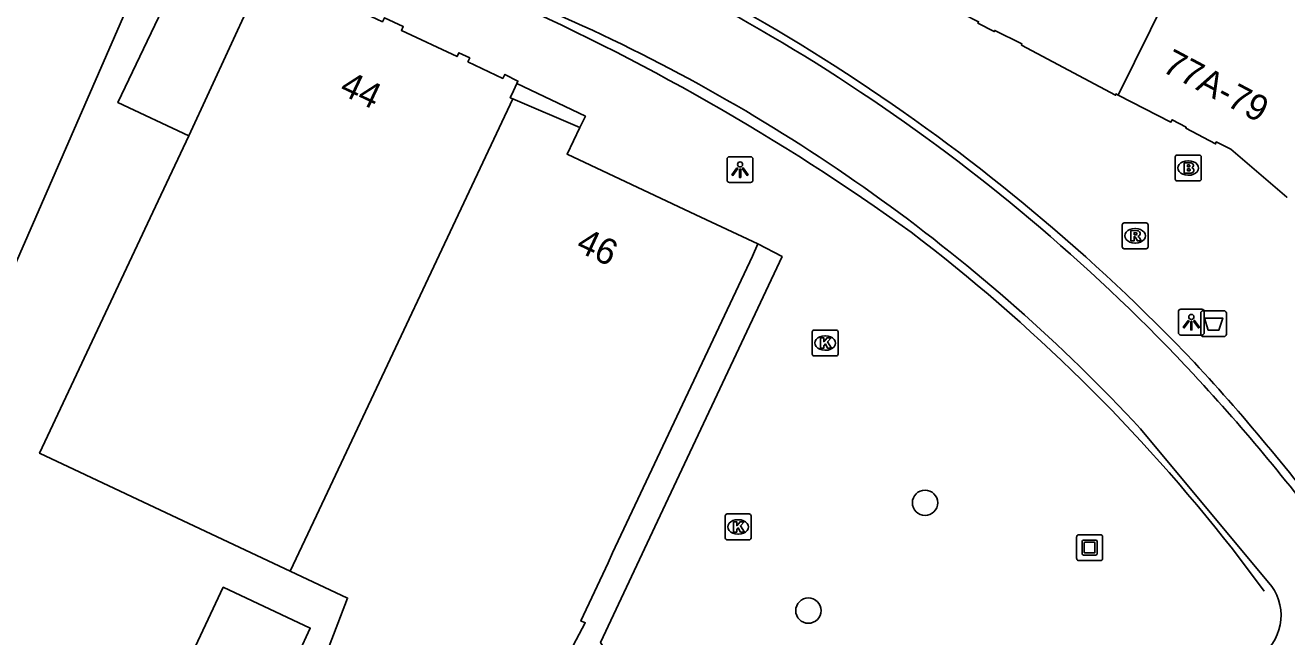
# Model space of a CAD drawing. Extents: x 161087 to 161922, y 382574 to 383873.
# Drawn here: x 161588.59 to 161637.33, y 382995.31 to 383018.93 of the extents above; entities that cross this region are included whole.
import ezdxf

# ---------------------------------------------------------------- set-up
doc = ezdxf.new("R2010")
doc.units = 0
for name, color, linetype in [('IMGEO_Afvalbak', 7, 'Continuous'), ('IMGEO_Boom', 7, 'Continuous'), ('IMGEO_Brandkraan', 7, 'Continuous'), ('IMGEO_Kolk', 7, 'Continuous'), ('IMGEO_Kunstobject', 7, 'Continuous'), ('IMGEO_Lichtpunt', 7, 'Continuous'), ('IMGEO_Lijnafwatering', 7, 'Continuous'), ('IMGEO_Pand', 7, 'Continuous'), ('IMGEO_Pand_nummerreeks', 7, 'Continuous'), ('IMGEO_Pand_overbouw', 7, 'Continuous'), ('IMGEO_Rioolput', 7, 'Continuous'), ('IMGEO_Voetgangersgebied_gesloten', 7, 'Continuous'), ('IMGEO_Voetgangersgebied_open', 7, 'Continuous')]:
    doc.layers.add(name, color=color, linetype=linetype)

msp = doc.modelspace()

# ---------------------------------------------------------------- linework, layer by layer
at = {"layer": 'IMGEO_Afvalbak'}
for p, q in [((161634.008, 383007.005), (161634.008, 383007.805)), ((161634.008, 383007.805), (161634.008, 383007.005)), ((161634.108, 383007.905), (161634.898, 383007.905)), ((161634.898, 383007.905), (161634.108, 383007.905)), ((161634.998, 383007.805), (161634.998, 383007.005)), ((161634.998, 383007.005), (161634.998, 383007.805)), ((161634.898, 383006.905), (161634.108, 383006.905)), ((161634.108, 383006.905), (161634.898, 383006.905))]:
    msp.add_line(p, q, dxfattribs=at)
msp.add_lwpolyline([(161634.151, 383007.619), (161634.855, 383007.619), (161634.706, 383007.149), (161634.3, 383007.149), (161634.151, 383007.619)], dxfattribs=at)
for centre, start, end in [((161634.108, 383007.805), 90, 180), ((161634.108, 383007.805), 90, 180), ((161634.898, 383007.805), 0, 90), ((161634.898, 383007.805), 360, 90), ((161634.108, 383007.005), 180, 270), ((161634.108, 383007.005), 180, 270), ((161634.898, 383007.005), 270, 0), ((161634.898, 383007.005), 270, 0)]:
    msp.add_arc(centre, 0.1, start, end, dxfattribs=at)
at = {"layer": 'IMGEO_Boom'}
for centre in [(161623.355, 383000.49), (161618.849, 382996.324)]:
    msp.add_circle(centre, 0.489, dxfattribs=at)
at = {"layer": 'IMGEO_Brandkraan'}
for p, q in [((161633.025, 383012.991), (161633.025, 383013.843)), ((161633.1, 383013.917), (161633.952, 383013.917)), ((161633.513, 383013.697), (161633.538, 383013.697)), ((161634.026, 383013.843), (161634.026, 383012.991)), ((161633.952, 383012.917), (161633.1, 383012.917)), ((161633.536, 383013.137), (161633.511, 383013.137))]:
    msp.add_line(p, q, dxfattribs=at)
for points in [[(161633.025, 383012.991), (161633.025, 383013.843)], [(161633.1, 383013.917), (161633.952, 383013.917)], [(161634.026, 383013.843), (161634.026, 383012.991)], [(161633.373, 383013.617), (161633.373, 383013.217), (161633.586, 383013.217)], [(161633.604, 383013.617), (161633.373, 383013.617)], [(161633.552, 383013.536), (161633.498, 383013.536), (161633.498, 383013.46)], [(161633.498, 383013.46), (161633.551, 383013.46)], [(161633.56, 383013.384), (161633.498, 383013.384), (161633.498, 383013.303)], [(161633.498, 383013.303), (161633.56, 383013.303)], [(161633.952, 383012.917), (161633.1, 383012.917)]]:
    msp.add_lwpolyline(points, dxfattribs=at)
for centre, radius, start, end in [((161633.102, 383013.841), 0.0765, 91.552, 178.448), ((161633.102, 383013.841), 0.0765, 91.552, 178.448), ((161633.95, 383013.841), 0.0765, 1.552, 88.448), ((161633.95, 383013.841), 0.0765, 1.552, 88.448), ((161633.553, 383013.498), 0.0379, 267.8285, 90.9355), ((161633.561, 383013.343), 0.0404, 269.8759, 90.5077), ((161633.592, 383013.468), 0.251, 268.6676, 293.5347), ((161633.608, 383013.472), 0.145, 59.4692, 91.5367), ((161633.633, 383013.519), 0.0922, 285.5137, 58.1501), ((161633.638, 383013.327), 0.105, 301.3115, 78.989), ((161633.102, 383012.993), 0.0765, 181.552, 268.448), ((161633.102, 383012.993), 0.0765, 181.552, 268.448), ((161633.95, 383012.993), 0.0765, 271.552, 358.448), ((161633.95, 383012.993), 0.0765, 271.552, 358.448)]:
    msp.add_arc(centre, radius, start, end, dxfattribs=at)
for centre, major_axis, ratio, start_param, end_param in [((161633.512, 383013.417), (-0.387, 0.002), 0.722429, 4.712389, 7.853982), ((161633.537, 383013.417), (-0.39, 0.002), 0.717154, 1.570796, 4.712389)]:
    msp.add_ellipse(centre, major_axis=major_axis, ratio=ratio, start_param=start_param, end_param=end_param, dxfattribs=at)
at = {"layer": 'IMGEO_Kolk'}
for p, q in [((161618.997, 383006.233), (161618.997, 383007.085)), ((161619.072, 383007.159), (161619.924, 383007.159)), ((161619.485, 383006.939), (161619.51, 383006.939)), ((161619.998, 383007.085), (161619.998, 383006.233)), ((161619.508, 383006.379), (161619.483, 383006.379)), ((161619.924, 383006.159), (161619.072, 383006.159)), ((161615.709, 383000.056), (161616.561, 383000.056)), ((161615.634, 382999.13), (161615.634, 382999.982)), ((161616.122, 382999.836), (161616.147, 382999.836)), ((161616.635, 382999.982), (161616.635, 382999.13)), ((161616.561, 382999.056), (161615.709, 382999.056)), ((161616.145, 382999.276), (161616.12, 382999.276))]:
    msp.add_line(p, q, dxfattribs=at)
for points in [[(161618.997, 383006.233), (161618.997, 383007.085)], [(161619.072, 383007.159), (161619.924, 383007.159)], [(161619.318, 383006.859), (161619.441, 383006.859), (161619.441, 383006.708), (161619.571, 383006.859), (161619.735, 383006.859), (161619.589, 383006.708), (161619.742, 383006.459), (161619.59, 383006.459), (161619.505, 383006.623), (161619.441, 383006.556), (161619.441, 383006.459), (161619.318, 383006.459), (161619.318, 383006.859)], [(161619.998, 383007.085), (161619.998, 383006.233)], [(161619.924, 383006.159), (161619.072, 383006.159)], [(161615.709, 383000.056), (161616.561, 383000.056)], [(161615.634, 382999.13), (161615.634, 382999.982)], [(161615.955, 382999.756), (161616.078, 382999.756), (161616.078, 382999.605), (161616.208, 382999.756), (161616.372, 382999.756), (161616.226, 382999.605), (161616.379, 382999.356), (161616.227, 382999.356), (161616.142, 382999.52), (161616.078, 382999.453), (161616.078, 382999.356), (161615.955, 382999.356), (161615.955, 382999.756)], [(161616.635, 382999.982), (161616.635, 382999.13)], [(161616.561, 382999.056), (161615.709, 382999.056)]]:
    msp.add_lwpolyline(points, dxfattribs=at)
for centre, start, end in [((161619.074, 383007.083), 91.552, 178.448), ((161619.074, 383007.083), 91.552, 178.448), ((161619.922, 383007.083), 1.552, 88.448), ((161619.922, 383007.083), 1.552, 88.448), ((161619.074, 383006.235), 181.552, 268.448), ((161619.074, 383006.235), 181.552, 268.448), ((161619.922, 383006.235), 271.552, 358.448), ((161619.922, 383006.235), 271.552, 358.448), ((161615.711, 382999.98), 91.552, 178.448), ((161615.711, 382999.98), 91.552, 178.448), ((161616.559, 382999.98), 1.552, 88.448), ((161616.559, 382999.98), 1.552, 88.448), ((161615.711, 382999.132), 181.552, 268.448), ((161615.711, 382999.132), 181.552, 268.448), ((161616.559, 382999.132), 271.552, 358.448), ((161616.559, 382999.132), 271.552, 358.448)]:
    msp.add_arc(centre, 0.0765, start, end, dxfattribs=at)
for centre, major_axis, ratio, start_param, end_param in [((161619.484, 383006.659), (-0.387, 0.002), 0.722429, 4.712389, 7.853982), ((161619.509, 383006.659), (-0.39, 0.002), 0.717154, 1.570796, 4.712389), ((161616.121, 382999.556), (-0.387, 0.002), 0.722429, 4.712389, 7.853982), ((161616.146, 382999.556), (-0.39, 0.002), 0.717154, 1.570796, 4.712389)]:
    msp.add_ellipse(centre, major_axis=major_axis, ratio=ratio, start_param=start_param, end_param=end_param, dxfattribs=at)
at = {"layer": 'IMGEO_Kunstobject'}
for p, q in [((161629.214, 382999.173), (161629.214, 382998.332)), ((161629.214, 382999.173), (161629.214, 382998.332)), ((161630.13, 382999.257), (161629.289, 382999.257)), ((161630.13, 382999.257), (161629.289, 382999.257)), ((161629.478, 382999.045), (161629.952, 382999.045)), ((161630.214, 382998.341), (161630.214, 382999.182)), ((161630.214, 382998.341), (161630.214, 382999.182)), ((161629.428, 382998.521), (161629.428, 382998.995)), ((161629.508, 382998.945), (161629.508, 382998.571)), ((161629.902, 382998.965), (161629.528, 382998.965)), ((161629.528, 382998.551), (161629.902, 382998.551)), ((161629.922, 382998.571), (161629.922, 382998.945)), ((161630.002, 382998.995), (161630.002, 382998.521)), ((161629.298, 382998.257), (161630.139, 382998.257)), ((161629.298, 382998.257), (161630.139, 382998.257)), ((161629.952, 382998.471), (161629.478, 382998.471))]:
    msp.add_line(p, q, dxfattribs=at)
for centre, radius, start, end in [((161629.292, 382999.179), 0.0779, 92.4484, 184.2845), ((161629.292, 382999.179), 0.0779, 92.4484, 184.2845), ((161629.478, 382998.995), 0.05, 90, 180), ((161629.952, 382998.995), 0.05, 360, 90), ((161630.136, 382999.179), 0.0779, 2.4484, 94.2845), ((161630.136, 382999.179), 0.0779, 2.4484, 94.2845), ((161629.528, 382998.945), 0.02, 90, 180), ((161629.528, 382998.571), 0.02, 180, 270), ((161629.902, 382998.945), 0.02, 360, 90), ((161629.902, 382998.571), 0.02, 270, 0), ((161629.292, 382998.335), 0.0779, 182.4484, 274.2845), ((161629.292, 382998.335), 0.0779, 182.4484, 274.2845), ((161629.478, 382998.521), 0.05, 180, 270), ((161629.952, 382998.521), 0.05, 270, 0), ((161630.136, 382998.335), 0.0779, 272.4484, 4.2845), ((161630.136, 382998.335), 0.0779, 272.4484, 4.2845)]:
    msp.add_arc(centre, radius, start, end, dxfattribs=at)
at = {"layer": 'IMGEO_Lichtpunt'}
for p, q in [((161615.71, 383013.759), (161615.71, 383012.952)), ((161615.71, 383013.759), (161615.71, 383012.952)), ((161616.612, 383013.854), (161615.804, 383013.854)), ((161616.612, 383013.854), (161615.804, 383013.854)), ((161616.706, 383012.952), (161616.706, 383013.759)), ((161616.706, 383012.952), (161616.706, 383013.759)), ((161615.804, 383012.858), (161616.612, 383012.858)), ((161615.804, 383012.858), (161616.612, 383012.858)), ((161633.146, 383007.868), (161633.146, 383007.061)), ((161633.146, 383007.868), (161633.146, 383007.061)), ((161634.048, 383007.963), (161633.24, 383007.963)), ((161634.048, 383007.963), (161633.24, 383007.963)), ((161634.142, 383007.061), (161634.142, 383007.868)), ((161634.142, 383007.061), (161634.142, 383007.868)), ((161633.24, 383006.967), (161634.048, 383006.967)), ((161633.24, 383006.967), (161634.048, 383006.967))]:
    msp.add_line(p, q, dxfattribs=at)
for points in [[(161616.084, 383013.423), (161616.123, 383013.395), (161615.935, 383013.133), (161615.897, 383013.16), (161616.084, 383013.423)], [(161616.186, 383013.375), (161616.233, 383013.375), (161616.233, 383013.053), (161616.186, 383013.053), (161616.186, 383013.375)], [(161616.296, 383013.395), (161616.334, 383013.422), (161616.521, 383013.16), (161616.482, 383013.132), (161616.296, 383013.395)], [(161633.52, 383007.532), (161633.559, 383007.504), (161633.371, 383007.242), (161633.333, 383007.269), (161633.52, 383007.532)], [(161633.622, 383007.484), (161633.669, 383007.484), (161633.669, 383007.162), (161633.622, 383007.162), (161633.622, 383007.484)], [(161633.732, 383007.504), (161633.77, 383007.531), (161633.957, 383007.269), (161633.918, 383007.241), (161633.732, 383007.504)]]:
    msp.add_lwpolyline(points, dxfattribs=at)
for centre in [(161616.209, 383013.557), (161633.645, 383007.666)]:
    msp.add_circle(centre, 0.0994, dxfattribs=at)
for centre, start, end in [((161615.804, 383013.759), 90, 180), ((161615.804, 383013.759), 90, 180), ((161616.612, 383013.759), 0, 90), ((161616.612, 383013.759), 0, 90), ((161615.804, 383012.952), 180, 270), ((161615.804, 383012.952), 180, 270), ((161616.612, 383012.952), 270, 0), ((161616.612, 383012.952), 270, 360), ((161633.24, 383007.868), 90, 180), ((161633.24, 383007.868), 90, 180), ((161634.048, 383007.868), 0, 90), ((161634.048, 383007.868), 0, 90), ((161633.24, 383007.061), 180, 270), ((161633.24, 383007.061), 180, 270), ((161634.048, 383007.061), 270, 0), ((161634.048, 383007.061), 270, 360)]:
    msp.add_arc(centre, 0.0946, start, end, dxfattribs=at)
at = {"layer": 'IMGEO_Lijnafwatering'}
msp.add_lwpolyline([(161636.459, 382997.073), (161635.231, 382998.711)], dxfattribs=at)
for centre, radius, start, end in [((161579.171, 382953.81), 75.463, 43.66446, 69.43511), ((161571.511, 382939.689), 87.797, 54.24429, 66.39142), ((161581.513, 382956.576), 68.271, 38.10929, 52.77417), ((161571.231, 382948.219), 85.079, 36.64081, 42.69607)]:
    msp.add_arc(centre, radius, start, end, dxfattribs=at)
at = {"layer": 'IMGEO_Pand'}
for points in [[(161640.737, 383034.802), (161638.738, 383032.194), (161635.573, 383026.502), (161635.821, 383026.367), (161630.82, 383016.229)], [(161593.938, 383022.832), (161587.851, 383008.898), (161582.318, 383000.765), (161580.327, 383001.446)], [(161597.828, 383020.995), (161597.271, 383019.756), (161594.908, 383014.656), (161593.731, 383012.151), (161589.147, 383002.399), (161594.251, 383000), (161598.828, 382997.849)], [(161597.828, 383020.995), (161597.945, 383021.255), (161597.998, 383021.332), (161598.514, 383021.101), (161598.437, 383020.938), (161599.775, 383020.306), (161599.845, 383020.467), (161600.281, 383020.265), (161600.207, 383020.111), (161602.39, 383019.064), (161602.469, 383019.223), (161603.195, 383018.878), (161603.127, 383018.732), (161605.275, 383017.721), (161605.346, 383017.87), (161605.765, 383017.67), (161605.696, 383017.518), (161607.043, 383016.877), (161607.126, 383017.031), (161607.624, 383016.773), (161607.579, 383016.676)], [(161630.82, 383016.229), (161630.721, 383016.28), (161630.716, 383016.23), (161627.079, 383018.166), (161627.1, 383018.21), (161626.051, 383018.728), (161626.028, 383018.684), (161625.395, 383019.012), (161625.424, 383019.068), (161622.995, 383020.312)], [(161607.426, 383016.088), (161607.328, 383016.13), (161607.453, 383016.403), (161607.579, 383016.676)], [(161607.426, 383016.088), (161599.842, 383000), (161598.828, 382997.849)], [(161610.019, 383014.978), (161607.426, 383016.088)], [(161637.344, 383012.284), (161637.333, 383012.295), (161635.168, 383014.151), (161634.604, 383014.423), (161634.582, 383014.346), (161633.431, 383014.957), (161633.451, 383014.988), (161632.905, 383015.281), (161632.857, 383015.192), (161630.82, 383016.229)], [(161610.019, 383014.978), (161609.529, 383013.953), (161614.496, 383011.607), (161616.9, 383010.49)], [(161613.548, 382989.184), (161611.428, 382992.314), (161611.542, 382992.377), (161610.98, 382993.206), (161610.494, 382993.892), (161609.762, 382994.974), (161610.225, 382995.855), (161610.052, 382995.927), (161611.111, 382998.168), (161611.284, 382998.552), (161616.692, 383010.008), (161616.9, 383010.49)], [(161598.828, 382997.849), (161601.047, 382996.806), (161600.06, 382994.238), (161599.144, 382994.669), (161599.604, 382995.647), (161596.24, 382997.228), (161594.387, 382993.284), (161597.148, 382989.08), (161597.712, 382988.242), (161600.333, 382984.347), (161603.102, 382980.202), (161603.453, 382980.439)]]:
    msp.add_lwpolyline(points, dxfattribs=at)
at = {"layer": 'IMGEO_Pand_overbouw'}
msp.add_lwpolyline([(161597.271, 383019.756), (161594.585, 383021.02), (161592.171, 383015.943), (161594.908, 383014.656)], close=True, dxfattribs=at)
at = {"layer": 'IMGEO_Rioolput'}
for p, q in [((161630.972, 383010.373), (161630.972, 383011.225)), ((161631.047, 383011.299), (161631.899, 383011.299)), ((161631.973, 383011.225), (161631.973, 383010.373)), ((161631.46, 383011.079), (161631.485, 383011.079)), ((161631.899, 383010.299), (161631.047, 383010.299)), ((161631.483, 383010.519), (161631.458, 383010.519))]:
    msp.add_line(p, q, dxfattribs=at)
for points in [[(161630.972, 383010.373), (161630.972, 383011.225)], [(161631.047, 383011.299), (161631.899, 383011.299)], [(161631.973, 383011.225), (161631.973, 383010.373)], [(161631.561, 383010.997), (161631.309, 383010.999), (161631.309, 383010.599)], [(161631.309, 383010.599), (161631.433, 383010.599), (161631.433, 383010.761), (161631.444, 383010.761)], [(161631.487, 383010.918), (161631.433, 383010.918), (161631.433, 383010.837)], [(161631.433, 383010.837), (161631.485, 383010.837)], [(161631.491, 383010.732), (161631.562, 383010.599), (161631.702, 383010.599), (161631.637, 383010.725)], [(161631.899, 383010.299), (161631.047, 383010.299)]]:
    msp.add_lwpolyline(points, dxfattribs=at)
for centre, radius, start, end in [((161631.049, 383011.223), 0.0765, 91.552, 178.448), ((161631.049, 383011.223), 0.0765, 91.552, 178.448), ((161631.897, 383011.223), 0.0765, 1.552, 88.448), ((161631.897, 383011.223), 0.0765, 1.552, 88.448), ((161631.443, 383010.708), 0.0533, 26.0293, 88.6989), ((161631.469, 383011.026), 0.19, 274.7715, 282.9687), ((161631.493, 383010.822), 0.0964, 77.0061, 93.1865), ((161631.507, 383010.879), 0.0378, 276.6634, 79.6772), ((161631.56, 383010.887), 0.109, 350.3612, 89.416), ((161631.558, 383010.887), 0.112, 277.5842, 350.9817), ((161631.542, 383010.672), 0.108, 29.5134, 73.7905), ((161631.049, 383010.375), 0.0765, 181.552, 268.448), ((161631.049, 383010.375), 0.0765, 181.552, 268.448), ((161631.897, 383010.375), 0.0765, 271.552, 358.448), ((161631.897, 383010.375), 0.0765, 271.552, 358.448)]:
    msp.add_arc(centre, radius, start, end, dxfattribs=at)
for centre, major_axis, ratio, start_param, end_param in [((161631.459, 383010.799), (-0.387, 0.002), 0.722429, 4.712389, 7.853982), ((161631.484, 383010.799), (-0.39, 0.002), 0.717154, 1.570796, 4.712389)]:
    msp.add_ellipse(centre, major_axis=major_axis, ratio=ratio, start_param=start_param, end_param=end_param, dxfattribs=at)
at = {"layer": 'IMGEO_Voetgangersgebied_gesloten'}
for points in [[(161610.121, 383018.913), (161573.744, 383035.403), (161568.118, 383038.081), (161562.264, 383041.226), (161530.386, 383059.686), (161528.822, 383060.639), (161492.002, 383082.168)], [(161636.754, 382997.262), (161631.68, 383003.35)]]:
    msp.add_lwpolyline(points, dxfattribs=at)
for centre, radius, start, end in [((161580.738, 382955.994), 72.481, 42.98401, 68.96781), ((161581.718, 382956.853), 68.251, 42.94267, 65.40784), ((161577.584, 382953.191), 76.699, 36.46871, 42.90917), ((161635.184, 382996.144), 1.927, 302.468, 35.4668)]:
    msp.add_arc(centre, radius, start, end, dxfattribs=at)
at = {"layer": 'IMGEO_Voetgangersgebied_open'}
for points in [[(161607.579, 383016.676), (161610.232, 383015.418), (161610.019, 383014.978)], [(161616.9, 383010.49), (161617.832, 383009.996), (161613.127, 383000), (161610.818, 382995.094), (161614.415, 382989.772), (161613.548, 382989.184)]]:
    msp.add_lwpolyline(points, dxfattribs=at)

# ---------------------------------------------------------------- texts
at = {"layer": 'IMGEO_Pand_nummerreeks'}
for s, rotation, p in [('77A-79', 332.0397, (161632.465, 383017.168)), ('44', 334.7555, (161600.685, 383016.3)), ('46', 334.8242, (161609.822, 383010.238))]:
    msp.add_text(s, height=1, rotation=rotation, dxfattribs=at).set_placement(p)

doc.saveas('drawing.dxf')
